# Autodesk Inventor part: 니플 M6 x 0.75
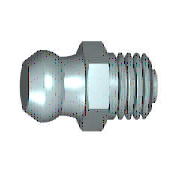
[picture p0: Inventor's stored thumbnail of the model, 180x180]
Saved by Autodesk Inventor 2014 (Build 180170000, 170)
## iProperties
IsCustomPart: 1
Created: 2012-02
Part Number: 니플 M6 x 0.75
Material: 강철, 연강
Description: 윤활 니플, 원추 유형 A
Document SubType Name: Modeling
Standard: JIS B 1575
Designer: mduedu
Standards Organization: JIS
Language: ko-KR
Size Designation: MT 6 x 0.75
Categories: <MemberInstance><Categories><Category DisplayName="기타 부품" InternalName="5aa15e00-363f-49f2-933f-16f664388e3f" Mnemonic="OTHER"><Category DisplayName="그리스 부속품" I
Density: 7.86 g/cm^3
Mass: 3.2546 g
Surface Area: 3.29319 cm^2
Volume: 0.414071 cm^3
Appearance: 금색
Author: mduedu
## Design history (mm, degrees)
sketch "스케치1"
  geometry: L1 (-8.8, 0)-(-8.8, 2.4); L2 (-8.8, 2.4)-(-7.335, 3.202); L3 (-8.8, 0)-(4.7, 0); L4 (4.7, 0)-(4.7, 1.5); L5 (4.7, 1.5)-(4, 1.5); L6 (4, 1.5)-(4, 3); L7 (4, 3)-(0, 3); L8 (-11.5, 0)-(7.4, 0) reference; L9 (0, -1.733)-(0, 10.398) reference; L10 (-3, 3.5)-(0, 3.5); L11 (0, 3.5)-(0, 3); A1 r 3.3 centre (-6.535, 0) between (-4.789, 2.8) and (-7.335, 3.202); A2 r 6 centre (-6.053, 8.665) between (-4.789, 2.8) and (-3, 3.5)
  constraints: 18 end point, 5 perpendicular, 4 point on circle, 2 centre point, 2 parallel, 2 point on line, 1 collinear, 1 vertical
  dimensions: "d0" = 13.5 distance between parallel lines of L1 L4 (= GL); "d1" = 5.6 diameter of A1.start L3 (= KGB2); "d2" = 0.7 distance between parallel lines of L4 L6 (= PHH); "d3" = 3 diameter of L5 L3 (= 0.5 x NND); "d4" = 6 diameter of L7 L3 (= NND); "d5" = 6.6 dimension on A1 L3 (= KR); "d6" = 4.8 diameter of L1.end L3 (= KGB1); "d7" = 6 radius of A2 (= RBN); "d11" = 7 diameter of L10.start L3 (= SW); "d14" = 3 distance of L10.start L10.end (= KOH); "d15" = 4 distance between parallel lines of L6 L11 (= NLG); "d61" = 7.33505 distance from line of L9 L2.end (computed from KGB1, KR, PHH, GL, NLG, VERS); "d62" = 6.53505 distance from line of L9 A1.centre (computed from NLG, GL, PHH, KR, KGB1)
revolve "본체" sketch "스케치1" stored, may be unused: angle "d25" = 90 deg
sketch "스케치2"
  geometry: L1 (2.021, 3.5)-(4.041, 0); L2 (4.041, 0)-(2.021, -3.5); L3 (2.021, -3.5)-(-2.021, -3.5); L4 (-2.021, -3.5)-(-4.041, 0); L5 (-4.041, 0)-(-2.021, 3.5); L6 (-2.021, 3.5)-(2.021, 3.5); C1 r 3.5 at (0, 0) reference; 1 further point
  constraints: 12 end point, 1 coincident, 1 horizontal, 1 tangent, 11 other
extrude "머리" join sketch "스케치2" distance "d17" = 3 (= KOH); taper "d18" = 0 deg
sketch "스케치3"
  geometry: L1 (2.687, 4.041)-(3, 4.041); L2 (3, 4.041)-(3, 3.5); L3 (3, 3.5)-(2.687, 4.041); L4 (0.313, 4.041)-(0, 4.041); L5 (0, 4.041)-(0, 3.5); L6 (0, 3.5)-(0.313, 4.041); L7 (3.6, 0)-(-0.6, 0) reference; L8 (0, 4.041)-(0, 2.021) reference; L9 (0, 4.041)-(3, 4.041) reference; L10 (3, 3.031)-(3, 4.041) reference
  constraints: 12 end point, 4 collinear, 3 perpendicular, 1 horizontal
  dimensions: "d19" = 3.5 distance from line of L5.end L7 (= 0.5 x SW); "d20" = 3.5 distance from line of L2.end L7 (= 0.5 x SW); "d21" = 30 deg angle of L6 L5; "d22" = 30 deg angle of L2 L3
revolve "모따기1" sketch "스케치3" stored, may be unused: angle "d56" = 90 deg
body "Solid1"
fillet "모깎기1" dims "d8" = 0.2 (= RR)
feature "스레드1" dims "d9" = 3.53991 (= NLG - GAL), "d10" = 0
chamfer "모따기2" distance "d23" = 0.46009 (= -0.5 x GD1 + 0.5 x NND); stored, may be unused: angle "d24" = 45 deg, second distance "d59" = 0.46009 (= -0.5 x GD1 + 0.5 x NND)
other parameters: "NLG" = 4 [user parameter; used in 4 equation terms], "GL" = 13.5 [user parameter; used in 3 equation terms], "NND" = 6 [user parameter; used in 4 equation terms], "KGB1" = 4.8 [user parameter; used in 3 equation terms], "KGB2" = 5.6 [user parameter; used in 1 equation term], "VERS" = 0.8 [user parameter; used in 1 equation term], "KR" = 6.6 [user parameter; used in 3 equation terms], "RBN" = 6 [user parameter; used in 1 equation term], "SW" = 7 [user parameter; used in 3 equation terms], "KOH" = 3 [user parameter; used in 2 equation terms], "GAL" = 0.46009 (= 0.61345 x PTC) [user parameter; used in 1 equation term], "FAWI" = 45 deg [user parameter], "PHH" = 0.7 [user parameter; used in 3 equation terms], "GD1" = 5.07983 (= THREADDIA - 1.2269 x PTC) [user parameter; used in 2 equation terms], "RR" = 0.2 [user parameter; used in 1 equation term], "d12" = 0, "d13" = 0, "GUL" = 0.46009 (= 0.61345 x PTC) [user parameter], "TPU" = 13.33333 (computed from PTC) [user parameter], "DULO" = 1.5 [user parameter], "PTC" = 0.75 [user parameter; used in 4 equation terms], "GEL" = 4 [user parameter], "THREADDIA" = 6 [user parameter; used in 1 equation term], "TOA" = 30 deg [user parameter]
